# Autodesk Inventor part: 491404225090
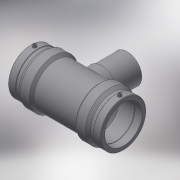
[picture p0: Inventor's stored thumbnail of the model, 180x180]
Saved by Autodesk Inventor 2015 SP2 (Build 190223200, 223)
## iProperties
Created: 2017-06
Part Number: 491404225090
Material: Generic
Description: PLASSON REDUCING TEE 225x90x225
Document SubType Name: Modeling
Designer: KIM
Mass: 11171.1 g
Surface Area: 8641.47 cm^2
Volume: 11171.1 cm^3
Density: 1 g/cm^3
Appearance: Default
Author: KIM
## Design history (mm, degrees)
derived "491404.ipt"
feature "Solid1::491404.ipt"
tag "TaggingFeature1"
body "Solid1"
other parameters: "d0" = 494, "d1" = 225, "d2" = 293, "d3" = 122, "d4" = 98.8, "d5" = 263.7, "d6" = 213.75, "d7" = 225, "d8" = 168 deg, "d10" = 48.8, "d11" = 16.26667, "d13" = 494, "d14" = 17.6296, "d17" = 202.5, "d18" = 225, "d19" = 3.52592, "d20" = 168 deg, "d22" = 272.49, "d23" = 293, "d25" = 135 deg, "d26" = 345.8, "d30" = 15, "d31" = 197.6, "d34" = 5 deg, "d35" = 15, "d39" = 5 deg, "d41" = 4, "d42" = 14, "d43" = 0, "d45" = 4, "d46" = 6, "d47" = 0, "d51" = 0, "d52" = 72, "d54" = 0, "d55" = 263.7, "d56" = 293, "d57" = 172.9, "d58" = 135 deg, "d59" = 122, "d60" = 122, "d61" = 135 deg, "d72" = 224.77, "d73" = 112.385, "d75" = 94.5, "d77" = 0, "d78" = 72, "d80" = 0, "d82" = 73.5, "d83" = 0, "d84" = 3, "d85" = 0, "d86" = 40.66667, "d87" = 267.0402, "d88" = 16.26667, "d89" = 3, "d90" = 0, "d_" = 225, "L_" = 494, "L_1" = 122, "D_" = 293, "d_2" = 12
